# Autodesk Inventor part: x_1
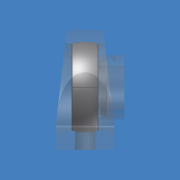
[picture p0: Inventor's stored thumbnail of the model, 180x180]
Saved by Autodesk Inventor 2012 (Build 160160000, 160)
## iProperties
Company: CAD-Verlag
Part Number: x_1
Document SubType Name: Modeling
Created: 2004-09
Material: Standard
Designer: Greiling
Manufacturer: Standard
Standards Organization: Custom
Density: 1 g/cm^3
Control State: 0
Master: False
Checked Out: False
Shininess: 64.0
Length Units: 11269
Angle Units: 11279
Time Units: 11290
Mass Units: 11283
Length Display Precision: 3
Angle Display Precision: 2
Compacted: True
Übersetzungsnorm: STEP AP214CD
Dateiname: w2c22665.stp
Vorprozessor: ACIS
Postprozessor: Build: 081d, Release: 8 SP1 - Date: Tue 01/26/2004
Gesendete Einheiten: MILLIMETERS
Unbestimmtheit: 1e-06
Density: 0.0
Volumn: 0.0
Area: 0.0
PropertySet Name: Model Information
Author: Jürgen Kronas
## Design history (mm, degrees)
feature "Basis1"
node "Volumenkörper1"
node "Volumenkörpern"
node "Oberflächenkörpern"
